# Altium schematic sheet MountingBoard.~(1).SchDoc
size E; Organization: Altium Limited; Address1: 3 Minna Close; Address2: Belrose; Address3: NSW 2085; Address4: Australia
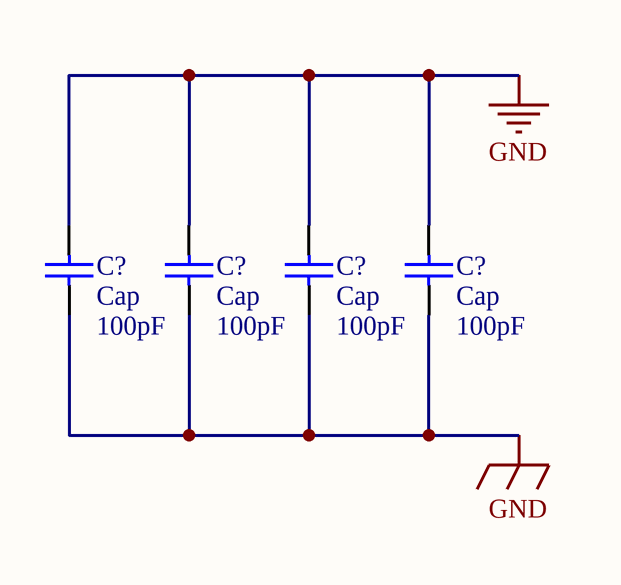
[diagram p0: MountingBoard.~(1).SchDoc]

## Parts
(Parts that share a designator on the sheet are numbered #1, #2 ... from top to bottom, then left to right.)
C?#1  Cap  value 100pF  [RAD-0.3]
C?#2  Cap  value 100pF  [RAD-0.3]
C?#3  Cap  value 100pF  [RAD-0.3]
C?#4  Cap  value 100pF  [RAD-0.3]

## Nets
GND: C?#1.1 C?#1.2 C?#2.1 C?#2.2 C?#3.1 C?#3.2 C?#4.1 C?#4.2

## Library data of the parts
C?#1-C?#4 = Cap: Capacitor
